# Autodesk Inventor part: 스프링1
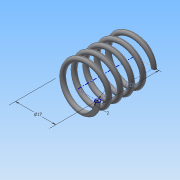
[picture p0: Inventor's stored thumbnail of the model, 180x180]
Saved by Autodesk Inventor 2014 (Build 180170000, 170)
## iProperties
Created: 2016-01
Part Number: 스프링1
Material: Generic
Document SubType Name: Modeling
Designer: Administrator
Density: 1 g/cm^3
Appearance: Default
Mass: 0.821689 g
Surface Area: 16.7182 cm^2
Volume: 0.821689 cm^3
Author: Administrator
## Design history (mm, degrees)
sketch "스케치1"
  geometry: L1 (0, 0)-(8.5, 0); L2 (8.5, 0)-(8.5, 20.5); L3 (8.5, 20.5)-(0, 20.5); L4 (0, 20.5)-(0, 0); C1 r 1 at (8.5, 0)
  constraints: 8 end point, 2 parallel, 1 centre point, 1 coincident, 1 horizontal, 1 perpendicular
  dimensions: "d0" = 17 diameter of L2 L4; "d1" = 20.5 distance of L1.end L2.end (derived); "d2" = 2 diameter of C1
feature "코일1" sketch "스케치1" pitch "d3" = 10; turns "d5" = 5; dims "d4" = 20.5 (= d1), "d6" = 0, angle "d7" = 90 deg, angle "d8" = 90 deg, "d9" = 0, "d10" = 0
node "작업 평면1"
sketch "스케치2"
  geometry: L1 (-9.5, 0)-(-7.5, 0) reference; 1 further point
  constraints: 1 horizontal alignment
extrude "돌출1" cut sketch "스케치2" distance "d12" = 10; taper "d13" = 0 deg
node "작업 평면2"
sketch "스케치3"
  geometry: L1 (-7.5, 0)-(-9.5, 0) reference; 1 further point
  constraints: 1 horizontal alignment
extrude "돌출2" cut sketch "스케치3" distance "d15" = 10; taper "d16" = 0 deg
node "솔리드1"
node "절단 모서리 투영1"
node "절단 모서리 투영2"
other parameters: "d11" = 0, "d14" = 20.5 (= d1)
